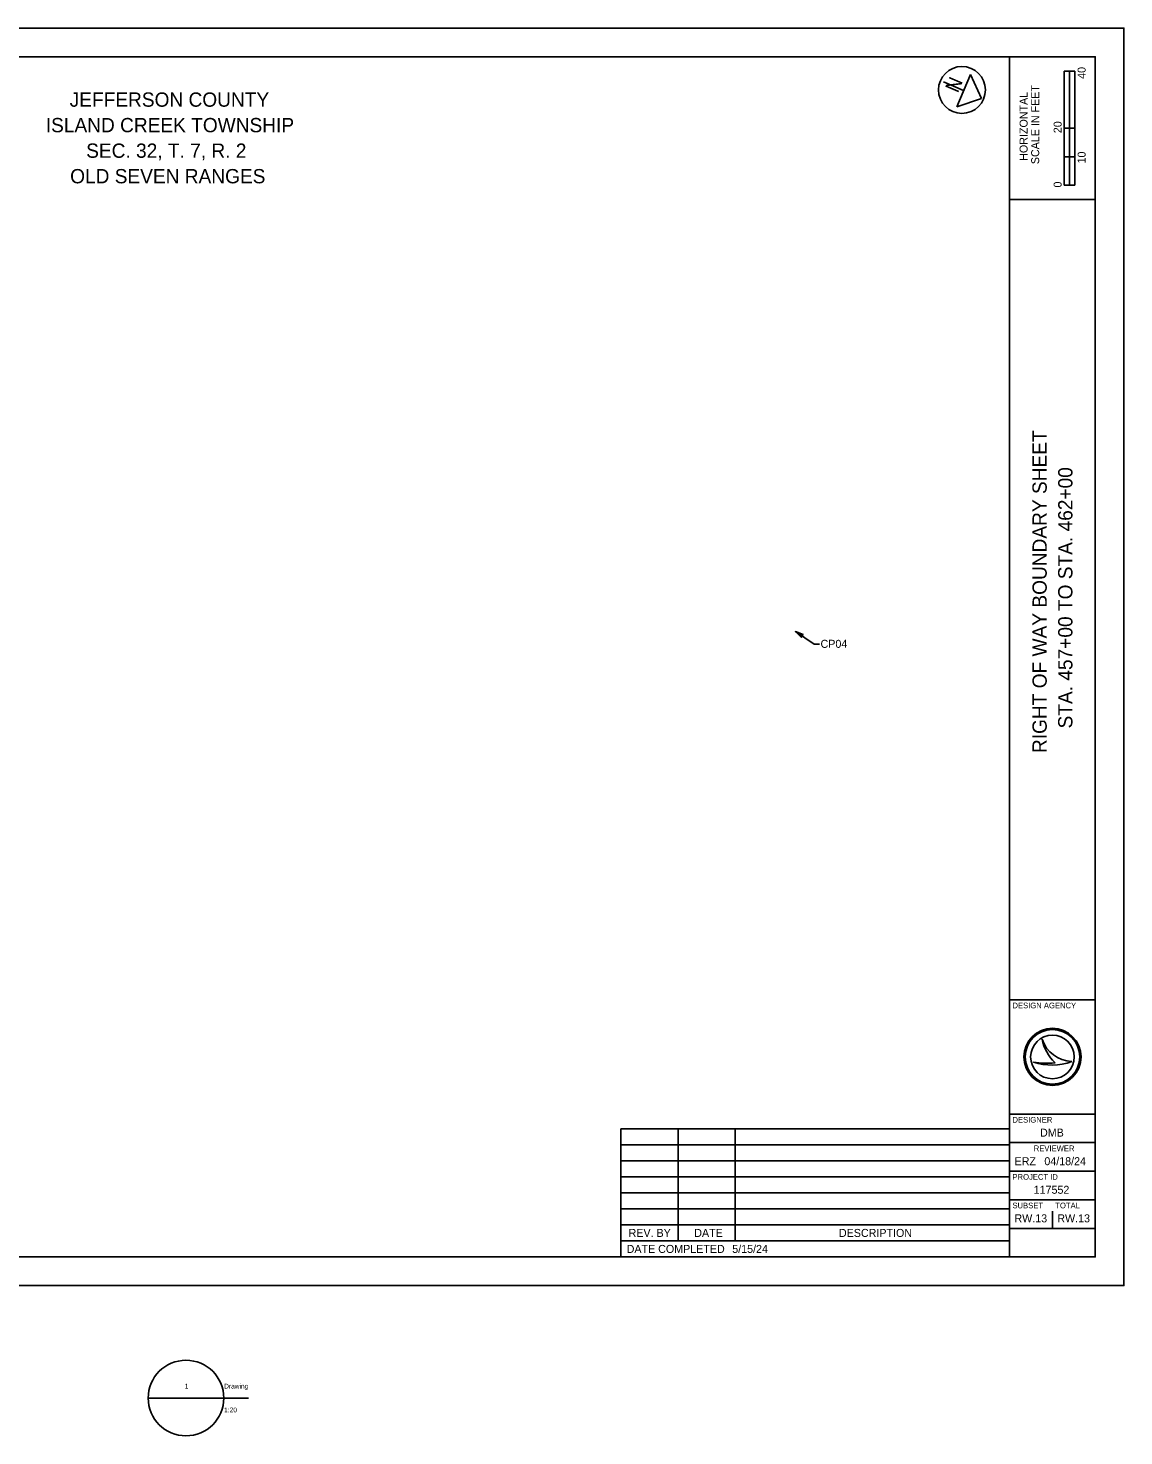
# Model space of a CAD drawing. Extents: x 0 to 680, y -53 to 440.
# Drawn here: x 296.4 to 680, y -52.6 to 440 of the extents above; entities that cross this region are included whole.
import ezdxf

# ---------------------------------------------------------------- set-up
doc = ezdxf.new("R2010")
doc.units = 0
for name, color, linetype in [('_CIVIL_CONSTRUCTION', 7, 'Continuous'), ('CM_Corridor_Final', 7, 'Continuous'), ('CM_Corridor_Range_Final', 7, 'Continuous'), ('MD_P_ACB_T', 7, 'Continuous'), ('MD_P_ACSC_B', 7, 'Continuous')]:
    doc.layers.add(name, color=color, linetype=linetype)

msp = doc.modelspace()

# ---------------------------------------------------------------- linework, layer by layer
at = {"layer": '_CIVIL_CONSTRUCTION'}
msp.add_lwpolyline([(0, 0), (680, 0), (680, 440), (0, 440)], close=True, dxfattribs=at)
at = {"layer": 'CM_Corridor_Final'}
for p, q in [((659.13, 385), (659.13, 425)), ((662.88, 425), (659.13, 425)), ((659.13, 405), (659.13, 425)), ((659.13, 425), (661, 425)), ((661, 425), (661.02, 425)), ((661.02, 425), (661.02, 405)), ((662.88, 425), (662.88, 385)), ((661.02, 405), (659.13, 405)), ((662.87, 405), (661, 405)), ((661, 405), (661, 395)), ((662.87, 395), (662.87, 405)), ((661, 395), (659.13, 395)), ((659.13, 395), (659.13, 385)), ((661, 385), (661, 395)), ((661, 395), (662.87, 395)), ((662.88, 385), (659.13, 385)), ((659.13, 385), (661, 385)), ((651.35, 86.19), (651.35, 86.19)), ((655, 80), (655, 80)), ((648.34, 78.19), (648.34, 78.19)), ((661.75, 78.37), (661.75, 78.37)), ((655, 20), (655, 26))]:
    msp.add_line(p, q, dxfattribs=at)
for radius in [10, 9.54, 9.54, 7.64]:
    msp.add_circle((655, 80), radius, dxfattribs=at)
for centre, radius, start, end in [((662.32, 89.95), 11.6, 198.9257, 198.9319), ((666.93, 89.4), 15.91, 191.6379, 191.6421), ((662.32, 89.95), 11.6, 198.9319, 267.1657), ((666.93, 89.4), 15.91, 191.6421, 226.0947), ((654.79, 97.4), 20.26, 251.4576, 290.0832), ((652.96, 103.09), 25.32, 259.4964, 259.4995), ((654.79, 97.4), 20.26, 251.4527, 251.4576), ((652.96, 103.09), 25.32, 259.4995, 276.6672)]:
    msp.add_arc(centre, radius, start, end, dxfattribs=at)
at = {"layer": 'CM_Corridor_Range_Final'}
for p, q in [((640, 10), (640, 430)), ((640, 380), (670, 380)), ((640, 100), (670, 100)), ((640, 60), (670, 60)), ((640, 50), (670, 50)), ((640, 40), (670, 40)), ((640, 30), (670, 30)), ((640, 20), (670, 20))]:
    msp.add_line(p, q, dxfattribs=at)
msp.add_lwpolyline([(30, 430), (670, 430), (670, 10), (30, 10)], close=True, dxfattribs=at)
at = {"layer": 'MD_P_ACB_T'}
msp.add_circle((623.31, 418.38), 8.2, dxfattribs=at)
at = {"layer": 'MD_P_ACSC_B'}
for p, q in [((626.34, 423.78), (621.48, 412.48)), ((630.18, 415.43), (626.34, 423.78)), ((623.91, 418.13), (616.8, 421.19)), ((621.48, 412.48), (630.18, 415.43)), ((503.93, 54.8), (503.93, 10)), ((503.93, 54.8), (640, 54.8)), ((523.93, 54.8), (523.93, 15.6)), ((543.93, 54.8), (543.93, 15.6)), ((503.93, 49.2), (640, 49.2)), ((503.93, 43.6), (640, 43.6)), ((503.93, 38), (640, 38)), ((503.93, 32.4), (640, 32.4)), ((503.93, 26.8), (640, 26.8)), ((503.93, 21.2), (640, 21.2)), ((503.93, 15.6), (640, 15.6)), ((640, 10), (640, 10)), ((338.41, -39.38), (364.87, -39.38)), ((351.75, -39.38), (373.55, -39.38))]:
    msp.add_line(p, q, dxfattribs=at)
msp.add_lwpolyline([(573.45, 224.49), (571.61, 224.49), (565.03, 228.84)], dxfattribs=at)
msp.add_lwpolyline([(567.68, 227.77), (567.06, 226.83), (565.03, 228.84)], close=True, dxfattribs=at)
for centre, radius in [((623.31, 418.38), 8.2), ((351.64, -39.38), 13.23)]:
    msp.add_circle(centre, radius, dxfattribs=at)

# ---------------------------------------------------------------- texts
at = {"layer": 'CM_Corridor_Final'}
for s, height, p in [('40', 2.8, (666.61, 422.25)), ('SCALE IN FEET', 2.8, (650.35, 392.41)), ('HORIZONTAL', 2.8, (646.3, 393.58)), ('20', 2.8, (658.21, 403.25)), ('10', 2.8, (666.61, 392.65)), ('0', 2.8, (658.21, 384.23)), ('RIGHT OF WAY BOUNDARY SHEET', 5, (653, 186.33)), ('STA. 457+00 TO STA. 462+00', 5, (662, 194.94))]:
    msp.add_text(s, height=height, rotation=90, dxfattribs=at).set_placement(p)
for s, height, p in [('             JEFFERSON COUNTY             ', 5, (286.77, 412.5)), ('           ISLAND CREEK TOWNSHIP          ', 5, (282.12, 403.57)), ('            SEC. 32, T. 7, R. 2           ', 5, (294.4, 394.63)), ('             OLD SEVEN RANGES             ', 5, (286.93, 385.7)), ('DESIGN AGENCY', 2, (641, 97)), ('DESIGNER', 2, (641, 57)), ('DMB', 2.8, (650.65, 52.1)), ('ERZ', 2.8, (641.74, 42.1)), ('REVIEWER', 2, (648.44, 47)), ('04/18/24', 2.8, (652.16, 42.1)), ('PROJECT ID', 2, (641, 37)), ('117552', 2.8, (648.42, 32.1)), ('SUBSET', 2, (641, 27)), ('RW.13', 2.8, (641.7, 22.1)), ('TOTAL', 2, (656, 27)), ('RW.13', 2.8, (656.7, 22.1))]:
    msp.add_text(s, height=height, dxfattribs=at).set_placement(p)
at = {"layer": 'MD_P_ACSC_B'}
msp.add_text('N', height=5, rotation=246.7033, dxfattribs=at).set_placement((619.16, 423.47))
for s, height, p in [('CP04', 2.8, (573.81, 223.15)), ('REV. BY', 2.8, (506.61, 17)), ('DATE', 2.8, (529.59, 17)), ('DESCRIPTION', 2.8, (580.25, 17)), ('DATE COMPLETED', 2.8, (505.93, 11.4)), ('5/15/24                            ', 2.8, (542.89, 11.4)), ('1', 1.67, (351.21, -36.05)), ('Drawing', 1.667, (365, -36.05)), ('1:20', 1.667, (365, -44.38))]:
    msp.add_text(s, height=height, dxfattribs=at).set_placement(p)

doc.saveas('drawing.dxf')
